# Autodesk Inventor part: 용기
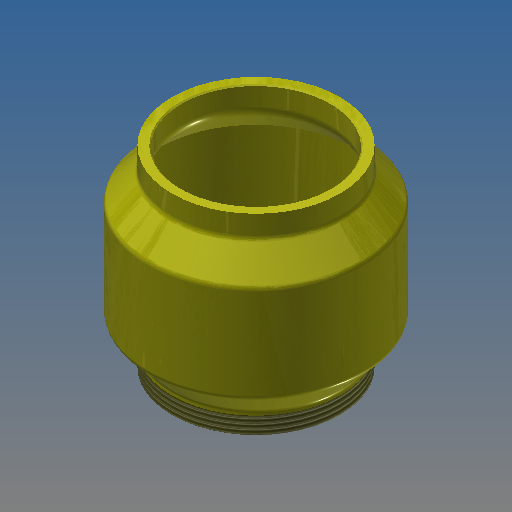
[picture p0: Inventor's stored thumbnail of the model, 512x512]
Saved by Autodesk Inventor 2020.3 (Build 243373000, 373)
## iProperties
Created: 2018-01
Part Number: 용기
Material: ABS 플라스틱
Document SubType Name: Modeling
Designer: mduedu
Density: 1 g/cm^3
Appearance: 노란색
Author: mduedu
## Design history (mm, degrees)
sketch "스케치1"
  geometry: L1 (0, 0)-(-35, 0); L2 (-35, 0)-(-35, 9); L3 (-35, 9)-(-45, 20); L4 (-45, 20)-(-45, 60); L5 (-45, 60)-(-35, 71); L6 (-35, 71)-(-35, 80); L7 (-35, 80)-(0, 80); L8 (0, 80)-(0, 0)
  constraints: 16 end point, 3 collinear, 3 parallel, 1 horizontal, 1 perpendicular
  dimensions: "d0" = 9 distance of L1.end L2.end; "d2" = 70 diameter of L2 L8; "d3" = 20 distance from line of L3.end L1; "d4" = 60 distance from line of L4.end L1; "d5" = 20 distance from line of L4.end L7; "d6" = 90 diameter of L4 L8
revolve "회전1" sketch "스케치1" stored, may be unused: angle "d7" = 90 deg
fillet "모깎기1" dims "d8" = 3
feature "쉘1" dims "d9" = 4
chamfer "모따기1" distance "d11" = 0.5; stored, may be unused: second distance "d12" = 2, angle "d13" = 45 deg
feature "스레드1" dims "d14" = 7, "d15" = 0
node "솔리드1"
